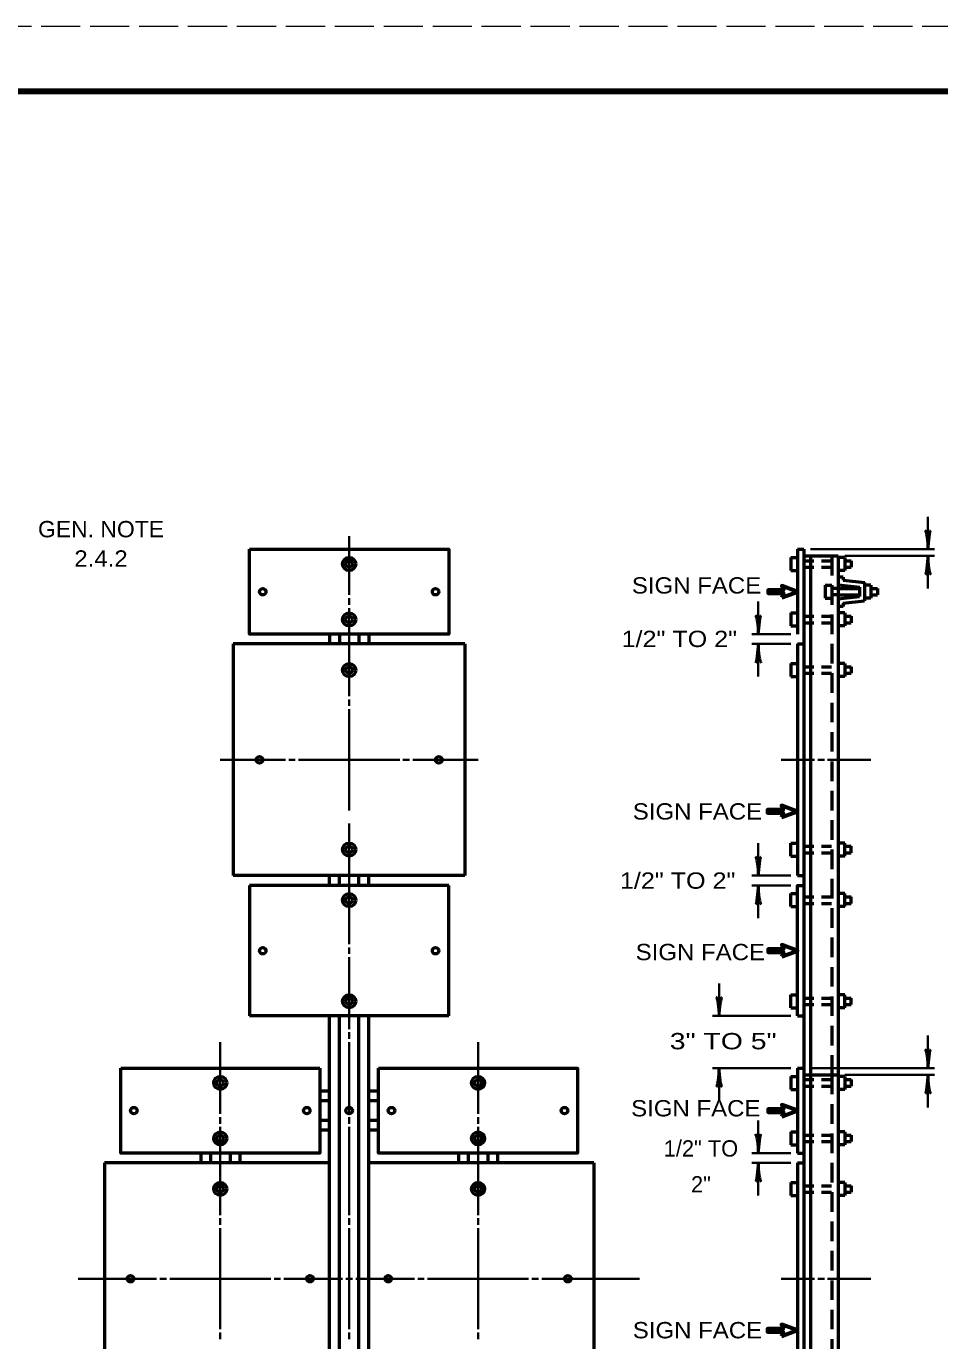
# Model space of a CAD drawing. Extents: x -45 to 635, y -382 to 59.
# Drawn here: x 147.9 to 287.9, y -142.8 to 58.5 of the extents above; entities that cross this region are included whole.
import ezdxf
from ezdxf.enums import TextEntityAlignment as Align

# ---------------------------------------------------------------- set-up
doc = ezdxf.new("R2010")
doc.units = 0
for name, pattern in [('LONG_DASHED', [7.5, 6, -1.5]), ('MEDIUM_DASHED', [4.5, 3, -1.5]), ('SHORT_DASHED', [2.7, 1.5, -1.2])]:
    doc.linetypes.add(name, pattern=pattern)
doc.layers.add('1', color=7, linetype='Continuous', lineweight=53)
doc.layers.add('61', color=7, linetype='Continuous', lineweight=35)

msp = doc.modelspace()

# ---------------------------------------------------------------- linework, layer by layer
at = {"layer": '1', "lineweight": 35}
for p, q in [((286.058, -21.59), (286.058, -16.59)), ((197.367, -19.59), (197.367, -28.59)), ((268.058, -21.59), (287.058, -21.59)), ((273.308, -22.59), (287.058, -22.59)), ((286.058, -27.59), (286.058, -22.59)), ((197.367, -29.09), (197.367, -30.09)), ((260.058, -34.59), (260.058, -29.59)), ((197.367, -30.59), (197.367, -44.09)), ((265.058, -34.59), (259.058, -34.59)), ((265.058, -36.09), (259.058, -36.09)), ((260.058, -41.09), (260.058, -36.09)), ((197.367, -44.59), (197.367, -45.59)), ((197.367, -46.09), (197.367, -61.59)), ((177.617, -53.84), (187.617, -53.84)), ((188.117, -53.84), (189.117, -53.84)), ((189.617, -53.84), (205.117, -53.84)), ((205.617, -53.84), (206.617, -53.84)), ((217.117, -53.84), (207.117, -53.84)), ((263.558, -53.84), (268.683, -53.84)), ((269.183, -53.84), (270.183, -53.84)), ((270.683, -53.84), (277.308, -53.84)), ((197.367, -63.59), (197.367, -82.09)), ((260.058, -71.59), (260.058, -66.59)), ((265.058, -71.59), (259.058, -71.59)), ((265.058, -73.09), (259.058, -73.09)), ((260.058, -78.09), (260.058, -73.09)), ((197.367, -82.59), (197.367, -83.59)), ((197.367, -95.09), (197.367, -84.09)), ((254.058, -93.09), (254.058, -88.09)), ((265.058, -93.09), (253.058, -93.09)), ((197.367, -96.59), (197.367, -95.59)), ((286.058, -101.09), (286.058, -96.09)), ((177.617, -97.09), (177.617, -108.09)), ((197.367, -108.09), (197.367, -97.09)), ((217.117, -97.09), (217.117, -108.09)), ((265.058, -101.09), (253.058, -101.09)), ((254.058, -106.09), (254.058, -101.09)), ((268.058, -101.09), (287.058, -101.09)), ((273.308, -102.09), (287.058, -102.09)), ((286.058, -107.09), (286.058, -102.09)), ((177.617, -108.59), (177.617, -109.59)), ((197.367, -109.59), (197.367, -108.59)), ((217.117, -108.59), (217.117, -109.59)), ((177.617, -110.09), (177.617, -123.59)), ((197.367, -123.59), (197.367, -110.09)), ((217.117, -110.09), (217.117, -123.59)), ((260.058, -114.09), (260.058, -109.09)), ((265.058, -114.09), (259.058, -114.09)), ((265.058, -115.59), (259.058, -115.59)), ((260.058, -120.59), (260.058, -115.59)), ((177.617, -124.09), (177.617, -125.09)), ((197.367, -125.09), (197.367, -124.09)), ((217.117, -124.09), (217.117, -125.09)), ((177.617, -125.59), (177.617, -141.09)), ((197.367, -141.09), (197.367, -125.59)), ((217.117, -125.59), (217.117, -141.09)), ((155.867, -133.34), (167.867, -133.34)), ((168.367, -133.34), (169.367, -133.34)), ((169.867, -133.34), (185.367, -133.34)), ((185.867, -133.34), (186.867, -133.34)), ((196.867, -133.34), (197.867, -133.34)), ((198.367, -133.34), (199.367, -133.34)), ((199.367, -133.34), (207.367, -133.34)), ((207.867, -133.34), (208.867, -133.34)), ((209.367, -133.34), (224.867, -133.34)), ((225.367, -133.34), (226.367, -133.34)), ((226.867, -133.34), (241.867, -133.34)), ((263.558, -133.34), (268.683, -133.34)), ((269.183, -133.34), (270.183, -133.34)), ((270.683, -133.34), (277.308, -133.34)), ((177.617, -141.59), (177.617, -142.59)), ((197.367, -142.59), (197.367, -141.59)), ((217.117, -141.59), (217.117, -142.59))]:
    msp.add_line(p, q, dxfattribs=at)
at = {"layer": '1'}
for p, q in [((266.058, -21.59), (266.058, -34.59)), ((266.058, -21.59), (267.058, -21.59)), ((267.058, -21.59), (267.058, -36.09)), ((265.058, -22.84), (265.058, -24.84)), ((265.058, -22.84), (266.058, -22.84)), ((267.058, -22.59), (272.308, -22.59)), ((268.058, -22.59), (268.058, -102.09)), ((272.308, -22.59), (272.308, -102.09)), ((273.308, -22.84), (272.308, -22.84)), ((273.308, -22.84), (273.308, -24.84)), ((273.308, -23.34), (274.308, -23.34)), ((274.308, -23.34), (274.308, -24.34)), ((265.058, -24.84), (266.058, -24.84)), ((273.308, -24.84), (272.308, -24.84)), ((273.058, -25.84), (272.308, -25.84)), ((273.058, -25.84), (273.058, -26.34)), ((273.308, -24.34), (274.308, -24.34)), ((270.308, -27.09), (270.308, -29.09)), ((270.308, -27.09), (271.308, -27.09)), ((272.308, -27.011), (275.558, -27.372)), ((272.308, -27.59), (275.558, -27.59)), ((273.058, -26.34), (276.308, -26.701)), ((275.558, -27.372), (275.558, -28.807)), ((276.308, -26.701), (276.308, -29.479)), ((277.308, -27.09), (276.308, -27.09)), ((277.308, -27.09), (277.308, -29.09)), ((277.308, -27.59), (278.308, -27.59)), ((278.308, -27.59), (278.308, -28.59)), ((270.308, -29.09), (271.308, -29.09)), ((272.308, -28.59), (275.558, -28.59)), ((272.308, -29.169), (275.558, -28.807)), ((273.058, -29.84), (276.308, -29.479)), ((273.058, -29.84), (273.058, -30.34)), ((277.308, -29.09), (276.308, -29.09)), ((277.308, -28.59), (278.308, -28.59)), ((265.058, -31.34), (265.058, -33.34)), ((265.058, -31.34), (266.058, -31.34)), ((273.058, -30.34), (272.308, -30.34)), ((273.308, -31.34), (272.308, -31.34)), ((273.308, -31.34), (273.308, -33.34)), ((273.308, -31.84), (274.308, -31.84)), ((274.308, -31.84), (274.308, -32.84)), ((265.058, -33.34), (266.058, -33.34)), ((273.308, -33.34), (272.308, -33.34)), ((273.308, -32.84), (274.308, -32.84)), ((215.117, -36.09), (179.617, -36.09)), ((179.617, -36.09), (179.617, -71.59)), ((194.367, -34.59), (194.367, -36.09)), ((195.867, -34.59), (195.867, -36.09)), ((198.867, -34.59), (198.867, -36.09)), ((200.367, -34.59), (200.367, -36.09)), ((215.117, -36.09), (215.117, -71.59)), ((266.058, -36.09), (266.058, -71.59)), ((266.058, -36.09), (267.058, -36.09)), ((267.058, -36.09), (267.058, -101.09)), ((265.058, -39.09), (265.058, -41.09)), ((265.058, -39.09), (266.058, -39.09)), ((273.308, -39.09), (272.308, -39.09)), ((273.308, -39.09), (273.308, -41.09)), ((273.308, -39.59), (274.308, -39.59)), ((274.308, -39.59), (274.308, -40.59)), ((265.058, -41.09), (266.058, -41.09)), ((273.308, -41.09), (272.308, -41.09)), ((273.308, -40.59), (274.308, -40.59)), ((265.058, -68.59), (265.058, -66.59)), ((265.058, -66.59), (266.058, -66.59)), ((273.308, -66.59), (272.308, -66.59)), ((273.308, -68.59), (273.308, -66.59)), ((273.308, -67.09), (274.308, -67.09)), ((273.308, -68.09), (274.308, -68.09)), ((274.308, -68.09), (274.308, -67.09)), ((265.058, -68.59), (266.058, -68.59)), ((273.308, -68.59), (272.308, -68.59)), ((215.117, -71.59), (179.617, -71.59)), ((194.367, -73.09), (194.367, -71.59)), ((195.867, -73.09), (195.867, -71.59)), ((198.867, -73.09), (198.867, -71.59)), ((200.367, -73.09), (200.367, -71.59)), ((266.058, -71.59), (267.058, -71.59)), ((212.617, -73.09), (182.117, -73.09)), ((182.117, -73.09), (182.117, -93.09)), ((212.617, -93.09), (212.617, -73.09)), ((265.058, -76.34), (265.058, -74.34)), ((265.058, -74.34), (266.058, -74.34)), ((273.308, -74.34), (272.308, -74.34)), ((273.308, -76.34), (273.308, -74.34)), ((265.058, -76.34), (266.058, -76.34)), ((273.308, -76.34), (272.308, -76.34)), ((273.308, -74.84), (274.308, -74.84)), ((273.308, -75.84), (274.308, -75.84)), ((274.308, -75.84), (274.308, -74.84)), ((265.058, -91.84), (265.058, -89.84)), ((265.058, -89.84), (266.058, -89.84)), ((273.308, -89.84), (272.308, -89.84)), ((273.308, -91.84), (273.308, -89.84)), ((273.308, -90.34), (274.308, -90.34)), ((274.308, -91.34), (274.308, -90.34)), ((265.058, -91.84), (266.058, -91.84)), ((273.308, -91.84), (272.308, -91.84)), ((273.308, -91.34), (274.308, -91.34)), ((212.617, -93.09), (182.117, -93.09)), ((194.367, -202.09), (194.367, -93.09)), ((195.867, -202.09), (195.867, -93.09)), ((198.867, -202.09), (198.867, -93.09)), ((200.367, -202.09), (200.367, -93.09)), ((266.058, -93.09), (267.058, -93.09)), ((162.367, -101.09), (192.867, -101.09)), ((265.058, -102.34), (265.058, -104.34)), ((265.058, -102.34), (266.058, -102.34)), ((266.058, -101.09), (266.058, -114.09)), ((266.058, -101.09), (267.058, -101.09)), ((267.058, -102.09), (272.308, -102.09)), ((268.058, -102.09), (268.058, -181.59)), ((272.308, -102.09), (272.308, -181.59)), ((273.308, -102.34), (272.308, -102.34)), ((273.308, -102.34), (273.308, -104.34)), ((194.367, -104.59), (192.867, -104.59)), ((201.867, -104.59), (200.367, -104.59)), ((265.058, -104.34), (266.058, -104.34)), ((273.308, -104.34), (272.308, -104.34)), ((273.308, -102.84), (274.308, -102.84)), ((273.308, -103.84), (274.308, -103.84)), ((274.308, -102.84), (274.308, -103.84)), ((194.367, -106.09), (192.867, -106.09)), ((201.867, -106.09), (200.367, -106.09)), ((194.367, -109.09), (192.867, -109.09)), ((194.367, -110.59), (192.867, -110.59)), ((201.867, -109.09), (200.367, -109.09)), ((201.867, -110.59), (200.367, -110.59)), ((265.058, -110.84), (265.058, -112.84)), ((265.058, -110.84), (266.058, -110.84)), ((273.308, -110.84), (272.308, -110.84)), ((273.308, -110.84), (273.308, -112.84)), ((273.308, -111.34), (274.308, -111.34)), ((273.308, -112.34), (274.308, -112.34)), ((274.308, -111.34), (274.308, -112.34)), ((174.617, -114.09), (174.617, -115.59)), ((176.117, -114.09), (176.117, -115.59)), ((179.117, -114.09), (179.117, -115.59)), ((180.617, -114.09), (180.617, -115.59)), ((214.117, -114.09), (214.117, -115.59)), ((215.617, -114.09), (215.617, -115.59)), ((218.617, -114.09), (218.617, -115.59)), ((220.117, -114.09), (220.117, -115.59)), ((265.058, -112.84), (266.058, -112.84)), ((266.058, -114.09), (267.058, -114.09)), ((273.308, -112.84), (272.308, -112.84)), ((194.367, -115.59), (159.867, -115.59)), ((159.867, -115.59), (159.867, -151.09)), ((234.867, -115.59), (200.367, -115.59)), ((234.867, -115.59), (234.867, -151.09)), ((266.058, -115.59), (266.058, -151.09)), ((266.058, -115.59), (267.058, -115.59)), ((265.058, -118.59), (265.058, -120.59)), ((265.058, -118.59), (266.058, -118.59)), ((273.308, -118.59), (272.308, -118.59)), ((273.308, -118.59), (273.308, -120.59)), ((265.058, -120.59), (266.058, -120.59)), ((273.308, -120.59), (272.308, -120.59)), ((273.308, -119.09), (274.308, -119.09)), ((273.308, -120.09), (274.308, -120.09)), ((274.308, -119.09), (274.308, -120.09))]:
    msp.add_line(p, q, dxfattribs=at)
at = {"layer": '1', "linetype": 'SHORT_DASHED'}
for p, q in [((267.058, -23.34), (272.308, -23.34)), ((267.058, -24.34), (272.308, -24.34)), ((272.308, -27.59), (271.308, -27.59)), ((272.308, -28.59), (271.308, -28.59)), ((267.058, -31.84), (272.308, -31.84)), ((267.058, -32.84), (272.308, -32.84)), ((267.058, -39.59), (272.308, -39.59)), ((267.058, -40.59), (272.308, -40.59)), ((267.058, -67.09), (272.308, -67.09)), ((267.058, -68.09), (272.308, -68.09)), ((267.058, -74.84), (272.308, -74.84)), ((267.058, -75.84), (272.308, -75.84)), ((267.058, -90.34), (272.308, -90.34)), ((267.058, -91.34), (272.308, -91.34)), ((267.058, -102.84), (272.308, -102.84)), ((267.058, -103.84), (272.308, -103.84)), ((267.058, -111.34), (272.308, -111.34)), ((267.058, -112.34), (272.308, -112.34)), ((267.058, -119.09), (272.308, -119.09)), ((267.058, -120.09), (272.308, -120.09))]:
    msp.add_line(p, q, dxfattribs=at)
at = {"layer": '1', "linetype": 'MEDIUM_DASHED'}
for p, q in [((271.308, -22.59), (271.308, -102.09)), ((271.308, -102.09), (271.308, -181.59))]:
    msp.add_line(p, q, dxfattribs=at)
at = {"layer": '1'}
for points in [[(182.117, -21.59), (212.617, -21.59), (212.617, -34.59), (182.117, -34.59)], [(201.867, -101.09), (232.367, -101.09), (232.367, -114.09), (201.867, -114.09)]]:
    msp.add_lwpolyline(points, close=True, dxfattribs=at)
at = {"layer": '1', "lineweight": 60}
for points in [[(263.673, -28.99), (266.058, -28.09), (263.673, -27.19), (263.943, -27.865), (261.558, -27.865), (261.558, -28.315), (263.943, -28.315)], [(263.605, -62.642), (265.99, -61.741), (263.605, -60.841), (263.875, -61.517), (261.49, -61.517), (261.49, -61.966), (263.875, -61.966)], [(263.673, -83.99), (266.058, -83.09), (263.673, -82.19), (263.943, -82.865), (261.558, -82.865), (261.558, -83.315), (263.943, -83.315)], [(263.673, -108.49), (266.058, -107.59), (263.673, -106.69), (263.943, -107.365), (261.558, -107.365), (261.558, -107.815), (263.943, -107.815)], [(263.605, -142.142), (265.99, -141.242), (263.605, -140.341), (263.875, -141.017), (261.49, -141.017), (261.49, -141.466), (263.875, -141.466)]]:
    msp.add_lwpolyline(points, close=True, dxfattribs=at)
at = {"layer": '1'}
for points in [[(266.058, -93.09), (266.058, -73.09), (267.058, -73.09)], [(192.867, -101.09), (192.867, -114.09), (162.367, -114.09), (162.367, -101.09)], [(267.058, -101.09), (267.058, -115.59), (267.058, -180.59)]]:
    msp.add_lwpolyline(points, dxfattribs=at)
at = {"layer": '1', "lineweight": 35}
msp.add_lwpolyline([(187.367, -133.34), (195.367, -133.34), (196.367, -133.34)], dxfattribs=at)
at = {"layer": '1'}
for centre, radius in [((197.367, -23.84), 1), ((197.367, -23.84), 0.5), ((184.117, -28.09), 0.5), ((210.617, -28.09), 0.5), ((197.367, -32.34), 1), ((197.367, -32.34), 0.5), ((197.367, -40.09), 1), ((197.367, -40.09), 0.5), ((183.617, -53.84), 0.5), ((211.117, -53.84), 0.5), ((197.367, -67.59), 1), ((197.367, -67.59), 0.5), ((197.367, -75.34), 1), ((197.367, -75.34), 0.5), ((184.117, -83.09), 0.5), ((210.617, -83.09), 0.5), ((197.367, -90.84), 1), ((197.367, -90.84), 0.5), ((177.617, -103.34), 1), ((217.117, -103.34), 1), ((177.617, -103.34), 0.5), ((217.117, -103.34), 0.5), ((164.367, -107.59), 0.5), ((190.867, -107.59), 0.5), ((197.367, -107.59), 0.5), ((203.867, -107.59), 0.5), ((230.367, -107.59), 0.5), ((177.617, -111.84), 1), ((177.617, -111.84), 0.5), ((217.117, -111.84), 1), ((217.117, -111.84), 0.5), ((177.617, -119.59), 1), ((217.117, -119.59), 1), ((177.617, -119.59), 0.5), ((217.117, -119.59), 0.5), ((163.867, -133.34), 0.5), ((191.367, -133.34), 0.5), ((203.367, -133.34), 0.5), ((230.867, -133.34), 0.5)]:
    msp.add_circle(centre, radius, dxfattribs=at)
at = {"layer": '1', "lineweight": 40}
for centre, major_axis, ratio, start_param, end_param in [((285.782, -20.499), (0.156, -1.786), 0.122415, 0.8963533, 3.1415927), ((285.782, -20.499), (0.156, -1.786), 0.122415, 0.8963533, 3.1415927), ((286.27, -20.469), (-0.176, -1.756), 0.07063, 3.1407148, 5.41811), ((286.27, -20.469), (-0.176, -1.756), 0.07063, 3.1407148, 5.41811), ((285.847, -23.71), (0.176, 1.756), 0.07063, 3.1407148, 5.41811), ((286.335, -23.681), (-0.156, 1.786), 0.122415, 0.8963533, 3.1415927), ((259.782, -33.499), (0.156, -1.786), 0.122415, 0.8963533, 3.1415927), ((259.782, -33.499), (0.156, -1.786), 0.122415, 0.8963533, 3.1415927), ((260.27, -33.469), (-0.176, -1.756), 0.07063, 3.1407148, 5.41811), ((260.27, -33.469), (-0.176, -1.756), 0.07063, 3.1407148, 5.41811), ((259.847, -37.21), (0.176, 1.756), 0.07063, 3.1407148, 5.41811), ((260.335, -37.181), (-0.156, 1.786), 0.122415, 0.8963533, 3.1415927), ((259.782, -70.499), (0.156, -1.786), 0.122415, 0.8963533, 3.1415927), ((259.782, -70.499), (0.156, -1.786), 0.122415, 0.8963533, 3.1415927), ((260.27, -70.469), (-0.176, -1.756), 0.07063, 3.1407148, 5.41811), ((260.27, -70.469), (-0.176, -1.756), 0.07063, 3.1407148, 5.41811), ((259.847, -74.21), (0.176, 1.756), 0.07063, 3.1407148, 5.41811), ((260.335, -74.181), (-0.156, 1.786), 0.122415, 0.8963533, 3.1415927), ((253.782, -91.999), (0.156, -1.786), 0.122415, 0.8963533, 3.1415927), ((253.782, -91.999), (0.156, -1.786), 0.122415, 0.8963533, 3.1415927), ((254.27, -91.969), (-0.176, -1.756), 0.07063, 3.1407148, 5.41811), ((254.27, -91.969), (-0.176, -1.756), 0.07063, 3.1407148, 5.41811), ((285.782, -99.999), (0.156, -1.786), 0.122415, 0.8963533, 3.1415927), ((285.782, -99.999), (0.156, -1.786), 0.122415, 0.8963533, 3.1415927), ((286.27, -99.969), (-0.176, -1.756), 0.07063, 3.1407148, 5.41811), ((286.27, -99.969), (-0.176, -1.756), 0.07063, 3.1407148, 5.41811), ((253.847, -102.21), (0.176, 1.756), 0.07063, 3.1407148, 5.41811), ((253.847, -102.21), (0.176, 1.756), 0.07063, 3.1407148, 5.41811), ((254.335, -102.181), (-0.156, 1.786), 0.122415, 0.8963533, 3.1415927), ((254.335, -102.181), (-0.156, 1.786), 0.122415, 0.8963533, 3.1415927), ((285.847, -103.21), (0.176, 1.756), 0.07063, 3.1407148, 5.41811), ((286.335, -103.181), (-0.156, 1.786), 0.122415, 0.8963533, 3.1415927), ((259.782, -112.999), (0.156, -1.786), 0.122415, 0.8963533, 3.1415927), ((259.782, -112.999), (0.156, -1.786), 0.122415, 0.8963533, 3.1415927), ((260.27, -112.969), (-0.176, -1.756), 0.07063, 3.1407148, 5.41811), ((260.27, -112.969), (-0.176, -1.756), 0.07063, 3.1407148, 5.41811), ((259.847, -116.71), (0.176, 1.756), 0.07063, 3.1407148, 5.41811), ((260.335, -116.681), (-0.156, 1.786), 0.122415, 0.8963533, 3.1415927)]:
    msp.add_ellipse(centre, major_axis=major_axis, ratio=ratio, start_param=start_param, end_param=end_param, dxfattribs=at)
at = {"layer": '61', "linetype": 'LONG_DASHED', "lineweight": 13}
msp.add_line((-44.831, 58.54), (635.189, 58.54), dxfattribs=at)
at = {"layer": '61', "lineweight": 158}
msp.add_lwpolyline([(624.209, 48.54), (-14.831, 48.54), (-14.831, -371.48)], dxfattribs=at)

# ---------------------------------------------------------------- texts
at = {"layer": '1'}
for s, width, p in [('GEN. NOTE', 1.05, (159.344, -19.75)), ('2.4.2', 1.1, (159.344, -24.25)), ('SIGN FACE', 1.1, (250.595, -28.37)), ('1/2" TO 2"', 1.15, (247.958, -36.566)), ('SIGN FACE', 1.1, (250.737, -62.998)), ('1/2" TO 2"', 1.15, (247.705, -73.593)), ('SIGN FACE', 1.1, (251.177, -84.539)), ('3" TO 5"', 1.3, (254.677, -98.194)), ('SIGN FACE', 1.1, (250.482, -108.475)), ('SIGN FACE', 1.1, (250.737, -142.475))]:
    msp.add_text(s, height=2.5, dxfattribs=dict(at, width=width)).set_placement(p, align=Align.CENTER)
for s, p in [('1/2" TO', (251.269, -114.631)), ('2"', (251.269, -120.131))]:
    msp.add_text(s, height=2.5, dxfattribs=at).set_placement(p, align=Align.CENTER)

doc.saveas('drawing.dxf')
